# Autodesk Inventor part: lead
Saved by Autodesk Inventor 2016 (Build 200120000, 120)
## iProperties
Created: 2016-09
Part Number: lead
Material: Generic
Document SubType Name: Modeling
Designer: Administrator
Appearance: Generic
Author: Administrator
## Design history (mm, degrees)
feature "Body1"
feature "Body2"
feature "Body3"
feature "Body4"
feature "Body8"
feature "Body12"
feature "Body16"
feature "Body7"
feature "Body11"
feature "Body15"
feature "Body6"
feature "Body10"
feature "Body14"
feature "Body5"
feature "Body9"
feature "Body13"
body "Solid1"
body "Solid2"
body "Solid3"
body "Solid4"
body "Solid5"
body "Solid6"
body "Solid7"
body "Solid8"
body "Solid9"
body "Solid10"
body "Solid11"
body "Solid12"
body "Solid13"
body "Solid14"
body "Solid15"
body "Solid16"
